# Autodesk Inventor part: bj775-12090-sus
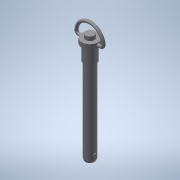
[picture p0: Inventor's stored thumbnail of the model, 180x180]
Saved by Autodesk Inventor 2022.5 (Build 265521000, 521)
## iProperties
Created: 2016-12
Part Number: bj775-12090-sus
Material: 一般
Document SubType Name: Modeling
Designer: imaocorp
Density: 1 g/cm^3
Appearance: 既定
Author: imaocorp
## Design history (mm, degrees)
node "bj775-12090-sus.x_t1"
node "bj775-12090-sus"
node "Base1"
